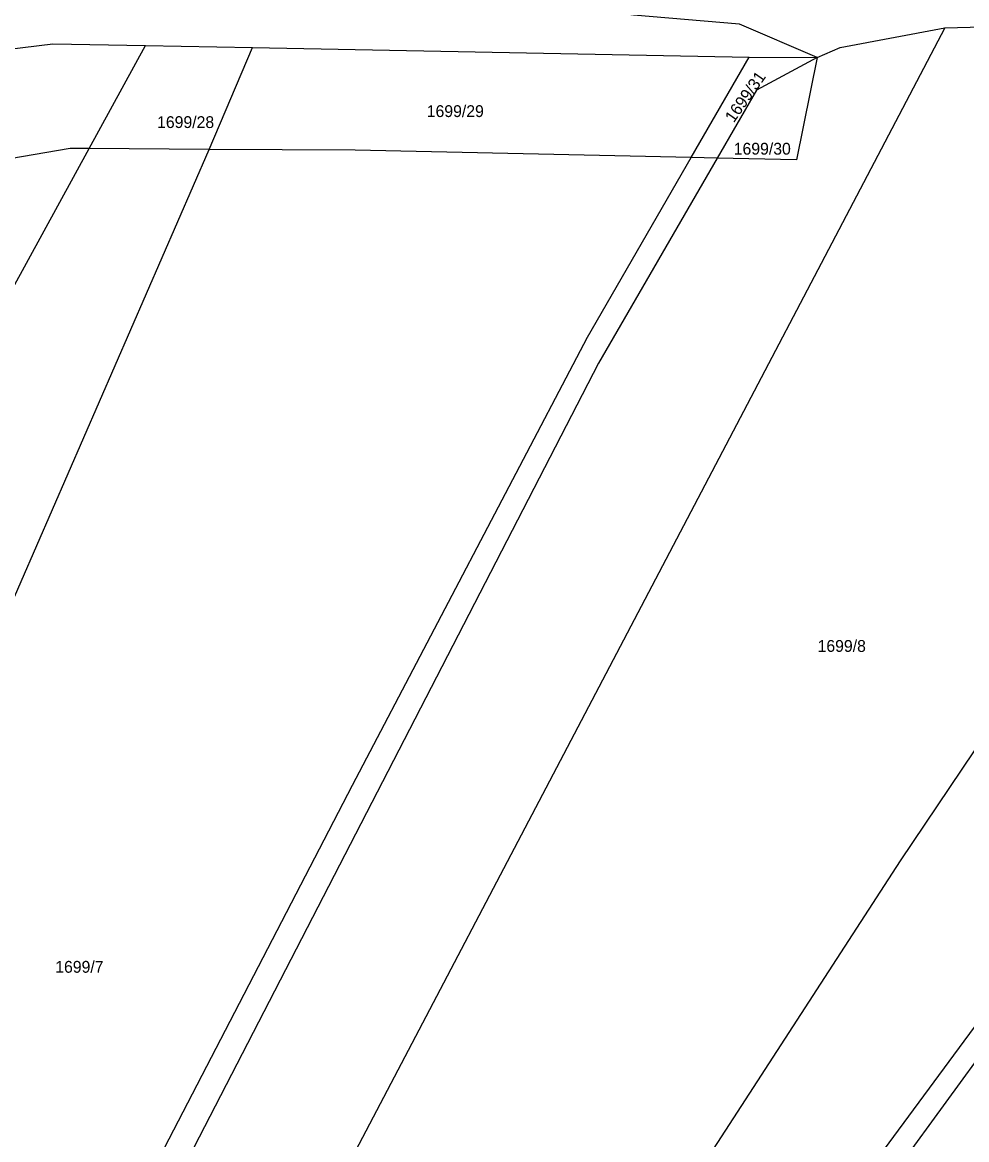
# Model space of a CAD drawing. Extents: x -679220 to -673243, y -1075091 to -1066557.
# Drawn here: x -677370.2 to -677234.3, y -1072096.6 to -1071935.7 of the extents above; entities that cross this region are included whole.
import ezdxf

# ---------------------------------------------------------------- set-up
doc = ezdxf.new("R2010")
doc.units = 0
for name, color, linetype in [('Hranice parcel', 7, 'Continuous'), ('Parcelní čísla', 7, 'Continuous'), ('Vnitřní kresba', 7, 'Continuous')]:
    doc.layers.add(name, color=color, linetype=linetype)

msp = doc.modelspace()

# ---------------------------------------------------------------- linework, layer by layer
at = {"layer": 'Hranice parcel'}
for p, q in [((-677360.6, -1071953.87), (-677352.5, -1071939.05)), ((-677352.5, -1071939.05), (-677337.08, -1071939.34)), ((-677343.33, -1071953.99), (-677337.08, -1071939.34)), ((-677337.08, -1071939.34), (-677265.6, -1071940.7)), ((-677273.95, -1071955.16), (-677265.6, -1071940.7)), ((-677265.6, -1071940.7), (-677255.81, -1071940.75)), ((-677343.33, -1071953.99), (-677360.6, -1071953.87)), ((-677270.2, -1071955.24), (-677273.95, -1071955.16))]:
    msp.add_line(p, q, dxfattribs=at)
for points in [[(-677255.81, -1071940.75), (-677266.99, -1071935.96), (-677282.24, -1071934.65), (-677362.7, -1071924.08), (-677378.67, -1071922.2), (-677406.61, -1071922.32), (-677449.1, -1071927.44), (-677452.43, -1071926.76)], [(-677237.41, -1071936.51), (-677328.88, -1072110.79), (-677291.9, -1072130.57)], [(-677255.81, -1071940.75), (-677252.51, -1071939.35), (-677237.41, -1071936.51)], [(-677237.41, -1071936.51), (-677219.22, -1071936.03), (-677183.21, -1071937.66), (-677165.39, -1071939.85)], [(-677393.33, -1071942.4), (-677376.88, -1071940.16), (-677365.82, -1071938.8), (-677352.5, -1071939.05)], [(-677291.9, -1072130.57), (-677243.78, -1072056.43), (-677165.39, -1071939.85)], [(-677255.81, -1071940.75), (-677264.54, -1071945.46), (-677270.2, -1071955.24)], [(-677255.81, -1071940.75), (-677258.75, -1071955.49), (-677270.2, -1071955.24)], [(-677138.12, -1071946.93), (-677209.73, -1072046.25), (-677227.4, -1072072.51), (-677269.53, -1072129.61), (-677328.01, -1072227.8), (-677386.47, -1072326.07), (-677421.34, -1072376.99), (-677442.67, -1072407.86), (-677458.14, -1072430.48)], [(-677503.95, -1072193.63), (-677486.55, -1072169.08), (-677441.67, -1072095.96), (-677405.46, -1072035.87), (-677360.6, -1071953.87)], [(-677469.31, -1072197.74), (-677439.08, -1072146.36), (-677400.91, -1072079.2), (-677374.92, -1072026.58), (-677343.33, -1071953.99)], [(-677360.6, -1071953.87), (-677363.34, -1071953.85), (-677404.53, -1071960.94)], [(-677273.95, -1071955.16), (-677322.31, -1071954.13), (-677343.33, -1071953.99)], [(-677419.19, -1072223.06), (-677385.01, -1072165.72), (-677322.67, -1072045.53), (-677288.88, -1071981.04), (-677273.95, -1071955.16)], [(-677270.2, -1071955.24), (-677287.29, -1071984.79), (-677359.52, -1072124.86), (-677384.77, -1072171.09), (-677395.64, -1072190.2), (-677409.69, -1072213.19)]]:
    msp.add_lwpolyline(points, dxfattribs=at)
at = {"layer": 'Vnitřní kresba'}
msp.add_line((-677266.43, -1072131.29), (-677225.03, -1072074.4), dxfattribs=at)

# ---------------------------------------------------------------- texts
at = {"layer": 'Parcelní čísla'}
msp.add_text('1699/31', height=1.7, rotation=55, dxfattribs=at).set_placement((-677267.81, -1071950.26))
for s, p in [('1699/29', (-677312, -1071949.34)), ('1699/28', (-677350.82, -1071950.92)), ('1699/30', (-677267.81, -1071954.75)), ('1699/8', (-677255.74, -1072026.34)), ('1699/7', (-677365.48, -1072072.54))]:
    msp.add_text(s, height=1.7, dxfattribs=at).set_placement(p)

doc.saveas('drawing.dxf')
